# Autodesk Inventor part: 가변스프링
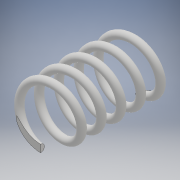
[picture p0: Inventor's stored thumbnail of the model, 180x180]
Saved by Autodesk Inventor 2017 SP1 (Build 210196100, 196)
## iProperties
Part Number: 가변스프링
Material: 일반
Document SubType Name: Modeling
Designer: 00-00
Density: 1 g/cm^3
Appearance: 기본값
Author: 00-00
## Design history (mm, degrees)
sketch "스케치1"
  geometry: L1 (0, 0)-(26.5, 0); L2 (26.5, 0)-(26.5, -7); L3 (26.5, -7)-(0, -7); L4 (0, -7)-(0, 0); C1 r 1 at (0, -7)
  constraints: 8 end point, 2 parallel, 1 centre point, 1 coincident, 1 horizontal, 1 perpendicular
  dimensions: "d0" = 14 diameter of L3 L1; "d1" = 2 diameter of C1; "d2" = 26.5 distance of L1.start L1.end (derived)
feature "코일1" sketch "스케치1" pitch "d3" = 10; turns "d5" = 5; dims "d4" = 26.5 (= d2), "d6" = 0, angle "d7" = 90 deg, angle "d8" = 90 deg, "d9" = 0, "d10" = 0
sketch "스케치2"
  geometry: L1 (-20.079, 26.5)-(20.079, 26.5); L2 (20.079, 26.5)-(20.079, 0); L3 (20.079, 0)-(-20.079, 0); L4 (-20.079, 0)-(-20.079, 26.5); 2 further points
  constraints: 8 end point, 2 parallel, 1 coincident, 1 horizontal, 1 midpoint, 1 perpendicular
  dimensions: "d11" = 40.15822 distance of L1.start L1.end; "d12" = 26.5 distance of L1.end L2.end (= d2)
extrude "돌출1" sketch "스케치2" stored distance "d13" = 63.25; taper "d14" = 0 deg
node "솔리드1"
